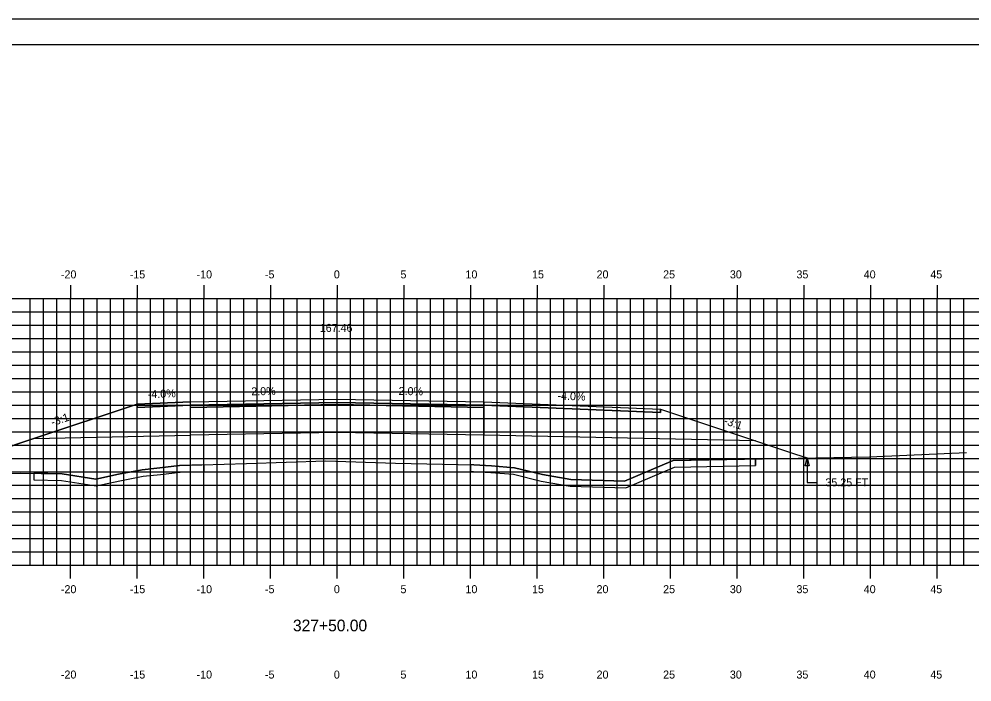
# Model space of a CAD drawing. Extents: x 1140759 to 1140929, y 608981 to 609091.
# Drawn here: x 1140818.2 to 1140889.6, y 609041.6 to 609091.3 of the extents above; entities that cross this region are included whole.
import ezdxf

# ---------------------------------------------------------------- set-up
doc = ezdxf.new("R2010")
doc.units = 0
for name, color, linetype in [('ANNOTATION', 7, 'Continuous'), ('BORDER', 7, 'Continuous'), ('D_Roadway_Centerline', 7, 'Continuous'), ('D_Roadway_Centerline_Text', 7, 'Continuous'), ('D_Roadway_Edge_Shoulder', 7, 'Continuous'), ('D_Roadway_Edge_TW', 7, 'Continuous'), ('D_Roadway_Pavement', 7, 'Continuous'), ('D_Roadway_SlopeLines', 7, 'Continuous'), ('D_Roadway_SubGrade', 7, 'Continuous'), ('D_Text_Standard', 7, 'Continuous'), ('H_V ANNOTATION', 7, 'Continuous'), ('MAJOR', 7, 'Continuous'), ('MINOR', 7, 'Continuous'), ('PLOT BOUNDARY', 7, 'Continuous'), ('S_Roadway_Centerline', 7, 'Continuous'), ('SHADING', 7, 'Continuous')]:
    doc.layers.add(name, color=color, linetype=linetype)

msp = doc.modelspace()

# ---------------------------------------------------------------- linework, layer by layer
msp.add_lwpolyline([(1140811.365, 609057.2), (1140816.276, 609058.837), (1140819.276, 609059.837), (1140827, 609062.411), (1140827.001, 609062.412), (1140831.001, 609062.572), (1140842.001, 609062.792), (1140853.001, 609062.572), (1140866.241, 609062.042), (1140873.375, 609059.664), (1140876.375, 609058.664), (1140877.252, 609058.372)])
at = {"layer": 'BORDER'}
msp.add_lwpolyline([(1140767.001, 608984.335), (1140927.001, 608984.335), (1140927.001, 609089.335), (1140767.001, 609089.335)], close=True, dxfattribs=at)
at = {"layer": 'D_Roadway_Edge_Shoulder'}
for points in [[(1140831.001, 609062.572), (1140827.001, 609062.412), (1140827.001, 609062.162), (1140831.001, 609062.322)], [(1140853.001, 609062.572), (1140866.241, 609062.042), (1140866.241, 609061.792), (1140853.001, 609062.322)]]:
    msp.add_lwpolyline(points, close=True, dxfattribs=at)
at = {"layer": 'D_Roadway_Edge_TW'}
msp.add_lwpolyline([(1140831.001, 609062.322), (1140831.001, 609062.572), (1140842.001, 609062.792), (1140853.001, 609062.572), (1140853.001, 609062.322), (1140842.001, 609062.542)], close=True, dxfattribs=at)
at = {"layer": 'D_Roadway_Pavement'}
msp.add_lwpolyline([(1140831.001, 609062.155), (1140831.001, 609062.322), (1140842.001, 609062.542), (1140853.001, 609062.322), (1140853.001, 609062.155), (1140842.001, 609062.375)], close=True, dxfattribs=at)
at = {"layer": 'D_Roadway_SlopeLines'}
for p, q in [((1140873.375, 609058.298), (1140873.375, 609057.798)), ((1140832.001, 609057.85), (1140832.001, 609057.35)), ((1140852.001, 609057.862), (1140852.001, 609057.362)), ((1140819.276, 609057.222), (1140819.276, 609056.722))]:
    msp.add_line(p, q, dxfattribs=at)
for points in [[(1140819.276, 609059.837), (1140816.276, 609058.837)], [(1140873.375, 609059.664), (1140876.375, 609058.664)], [(1140876.375, 609058.664), (1140877.252, 609058.372)], [(1140852.001, 609057.362), (1140852.225, 609057.357), (1140853.538, 609057.272), (1140855.215, 609057.147), (1140857.304, 609056.635), (1140859.464, 609056.256), (1140863.641, 609056.133), (1140867.31, 609057.681), (1140873.375, 609057.797)], [(1140819.276, 609056.723), (1140821.351, 609056.691), (1140823.935, 609056.277), (1140825.718, 609056.669), (1140827.469, 609057), (1140828.757, 609057.134), (1140830.231, 609057.298), (1140832.001, 609057.351)]]:
    msp.add_lwpolyline(points, dxfattribs=at)
at = {"layer": 'D_Roadway_SubGrade'}
for points in [[(1140831.001, 609062.155), (1140831.001, 609062.322), (1140827.001, 609062.162), (1140827.001, 609062.412), (1140827, 609062.411), (1140819.276, 609059.837), (1140831.001, 609060.071)], [(1140831.001, 609060.071), (1140831.001, 609062.155), (1140842.001, 609062.375), (1140853.001, 609062.155), (1140853.001, 609060.072), (1140842.001, 609060.292)], [(1140853.001, 609062.155), (1140853.001, 609062.322), (1140866.241, 609061.792), (1140866.241, 609062.042), (1140866.241, 609062.042), (1140873.375, 609059.664), (1140853.001, 609060.072)]]:
    msp.add_lwpolyline(points, close=True, dxfattribs=at)
at = {"layer": 'D_Text_Standard'}
msp.add_lwpolyline([(1140877.252, 609058.372), (1140877.397, 609057.79), (1140877.106, 609057.79)], close=True, dxfattribs=at)
msp.add_lwpolyline([(1140877.252, 609058.372), (1140877.251, 609056.542), (1140877.931, 609056.542)], dxfattribs=at)
at = {"layer": 'MAJOR'}
for p, q in [((1140822.001, 609071.337), (1140822.001, 609070.335)), ((1140827.001, 609071.337), (1140827.001, 609070.335)), ((1140832.001, 609071.337), (1140832.001, 609070.335)), ((1140837.001, 609071.337), (1140837.001, 609070.335)), ((1140842.001, 609071.337), (1140842.001, 609070.335)), ((1140847.001, 609071.337), (1140847.001, 609070.335)), ((1140852.001, 609071.337), (1140852.001, 609070.335)), ((1140857.001, 609071.337), (1140857.001, 609070.335)), ((1140862.001, 609071.337), (1140862.001, 609070.335)), ((1140867.001, 609071.337), (1140867.001, 609070.335)), ((1140872.001, 609071.337), (1140872.001, 609070.335)), ((1140877.001, 609071.337), (1140877.001, 609070.335)), ((1140882.001, 609071.337), (1140882.001, 609070.335)), ((1140887.001, 609071.337), (1140887.001, 609070.335)), ((1140772.001, 609070.335), (1140912.001, 609070.335)), ((1140772.001, 609070.335), (1140912.001, 609070.335)), ((1140822.001, 609050.335), (1140822.001, 609070.335)), ((1140827.001, 609050.335), (1140827.001, 609070.335)), ((1140832.001, 609050.335), (1140832.001, 609070.335)), ((1140837.001, 609050.335), (1140837.001, 609070.335)), ((1140842.001, 609050.335), (1140842.001, 609070.335)), ((1140847.001, 609050.335), (1140847.001, 609070.335)), ((1140852.001, 609050.335), (1140852.001, 609070.335)), ((1140857.001, 609050.335), (1140857.001, 609070.335)), ((1140862.001, 609050.335), (1140862.001, 609070.335)), ((1140867.001, 609050.335), (1140867.001, 609070.335)), ((1140872.001, 609050.335), (1140872.001, 609070.335)), ((1140877.001, 609050.335), (1140877.001, 609070.335)), ((1140882.001, 609050.335), (1140882.001, 609070.335)), ((1140887.001, 609050.335), (1140887.001, 609070.335)), ((1140772.001, 609065.335), (1140912.001, 609065.335)), ((1140772.001, 609060.335), (1140912.001, 609060.335)), ((1140772.001, 609055.335), (1140912.001, 609055.335)), ((1140772.001, 609050.335), (1140912.001, 609050.335)), ((1140772.001, 609050.335), (1140912.001, 609050.335)), ((1140822.001, 609049.333), (1140822.001, 609050.335)), ((1140827.001, 609049.333), (1140827.001, 609050.335)), ((1140832.001, 609049.333), (1140832.001, 609050.335)), ((1140837.001, 609049.333), (1140837.001, 609050.335)), ((1140842.001, 609049.333), (1140842.001, 609050.335)), ((1140847.001, 609049.333), (1140847.001, 609050.335)), ((1140852.001, 609049.333), (1140852.001, 609050.335)), ((1140857.001, 609049.333), (1140857.001, 609050.335)), ((1140862.001, 609049.333), (1140862.001, 609050.335)), ((1140867.001, 609049.333), (1140867.001, 609050.335)), ((1140872.001, 609049.333), (1140872.001, 609050.335)), ((1140877.001, 609049.333), (1140877.001, 609050.335)), ((1140882.001, 609049.333), (1140882.001, 609050.335)), ((1140887.001, 609049.333), (1140887.001, 609050.335))]:
    msp.add_line(p, q, dxfattribs=at)
at = {"layer": 'MINOR'}
for p, q in [((1140819.001, 609050.335), (1140819.001, 609070.335)), ((1140820.001, 609050.335), (1140820.001, 609070.335)), ((1140821.001, 609050.335), (1140821.001, 609070.335)), ((1140823.001, 609050.335), (1140823.001, 609070.335)), ((1140824.001, 609050.335), (1140824.001, 609070.335)), ((1140825.001, 609050.335), (1140825.001, 609070.335)), ((1140826.001, 609050.335), (1140826.001, 609070.335)), ((1140828.001, 609050.335), (1140828.001, 609070.335)), ((1140829.001, 609050.335), (1140829.001, 609070.335)), ((1140830.001, 609050.335), (1140830.001, 609070.335)), ((1140831.001, 609050.335), (1140831.001, 609070.335)), ((1140833.001, 609050.335), (1140833.001, 609070.335)), ((1140834.001, 609050.335), (1140834.001, 609070.335)), ((1140835.001, 609050.335), (1140835.001, 609070.335)), ((1140836.001, 609050.335), (1140836.001, 609070.335)), ((1140838.001, 609050.335), (1140838.001, 609070.335)), ((1140839.001, 609050.335), (1140839.001, 609070.335)), ((1140840.001, 609050.335), (1140840.001, 609070.335)), ((1140841.001, 609050.335), (1140841.001, 609070.335)), ((1140843.001, 609050.335), (1140843.001, 609070.335)), ((1140844.001, 609050.335), (1140844.001, 609070.335)), ((1140845.001, 609050.335), (1140845.001, 609070.335)), ((1140846.001, 609050.335), (1140846.001, 609070.335)), ((1140848.001, 609050.335), (1140848.001, 609070.335)), ((1140849.001, 609050.335), (1140849.001, 609070.335)), ((1140850.001, 609050.335), (1140850.001, 609070.335)), ((1140851.001, 609050.335), (1140851.001, 609070.335)), ((1140853.001, 609050.335), (1140853.001, 609070.335)), ((1140854.001, 609050.335), (1140854.001, 609070.335)), ((1140855.001, 609050.335), (1140855.001, 609070.335)), ((1140856.001, 609050.335), (1140856.001, 609070.335)), ((1140858.001, 609050.335), (1140858.001, 609070.335)), ((1140859.001, 609050.335), (1140859.001, 609070.335)), ((1140860.001, 609050.335), (1140860.001, 609070.335)), ((1140861.001, 609050.335), (1140861.001, 609070.335)), ((1140863.001, 609050.335), (1140863.001, 609070.335)), ((1140864.001, 609050.335), (1140864.001, 609070.335)), ((1140865.001, 609050.335), (1140865.001, 609070.335)), ((1140866.001, 609050.335), (1140866.001, 609070.335)), ((1140868.001, 609050.335), (1140868.001, 609070.335)), ((1140869.001, 609050.335), (1140869.001, 609070.335)), ((1140870.001, 609050.335), (1140870.001, 609070.335)), ((1140871.001, 609050.335), (1140871.001, 609070.335)), ((1140873.001, 609050.335), (1140873.001, 609070.335)), ((1140874.001, 609050.335), (1140874.001, 609070.335)), ((1140875.001, 609050.335), (1140875.001, 609070.335)), ((1140876.001, 609050.335), (1140876.001, 609070.335)), ((1140878.001, 609050.335), (1140878.001, 609070.335)), ((1140879.001, 609050.335), (1140879.001, 609070.335)), ((1140880.001, 609050.335), (1140880.001, 609070.335)), ((1140881.001, 609050.335), (1140881.001, 609070.335)), ((1140883.001, 609050.335), (1140883.001, 609070.335)), ((1140884.001, 609050.335), (1140884.001, 609070.335)), ((1140885.001, 609050.335), (1140885.001, 609070.335)), ((1140886.001, 609050.335), (1140886.001, 609070.335)), ((1140888.001, 609050.335), (1140888.001, 609070.335)), ((1140889.001, 609050.335), (1140889.001, 609070.335)), ((1140772.001, 609069.335), (1140912.001, 609069.335)), ((1140772.001, 609068.335), (1140912.001, 609068.335)), ((1140772.001, 609067.335), (1140912.001, 609067.335)), ((1140772.001, 609066.335), (1140912.001, 609066.335)), ((1140772.001, 609064.335), (1140912.001, 609064.335)), ((1140772.001, 609063.335), (1140912.001, 609063.335)), ((1140772.001, 609062.335), (1140912.001, 609062.335)), ((1140772.001, 609061.335), (1140912.001, 609061.335)), ((1140772.001, 609059.335), (1140912.001, 609059.335)), ((1140772.001, 609058.335), (1140912.001, 609058.335)), ((1140772.001, 609057.335), (1140912.001, 609057.335)), ((1140772.001, 609056.335), (1140912.001, 609056.335)), ((1140772.001, 609054.335), (1140912.001, 609054.335)), ((1140772.001, 609053.335), (1140912.001, 609053.335)), ((1140772.001, 609052.335), (1140912.001, 609052.335)), ((1140772.001, 609051.335), (1140912.001, 609051.335))]:
    msp.add_line(p, q, dxfattribs=at)
at = {"layer": 'PLOT BOUNDARY'}
msp.add_lwpolyline([(1140758.908, 608981.276), (1140928.908, 608981.276), (1140928.908, 609091.276), (1140758.908, 609091.276)], close=True, dxfattribs=at)
at = {"layer": 'S_Roadway_Centerline'}
msp.add_lwpolyline([(1140801.566, 609057.193), (1140812.339, 609057.2), (1140818.229, 609057.238), (1140821.395, 609057.189), (1140823.921, 609056.785), (1140825.618, 609057.158), (1140827.397, 609057.494), (1140828.704, 609057.63), (1140830.196, 609057.796), (1140835.206, 609057.946), (1140841.168, 609058.151), (1140846.371, 609057.971), (1140852.246, 609057.857), (1140853.573, 609057.771), (1140855.293, 609057.642), (1140857.407, 609057.124), (1140859.515, 609056.755), (1140863.547, 609056.636), (1140867.204, 609058.18), (1140881.91, 609058.461), (1140889.197, 609058.77)], dxfattribs=at)
at = {"layer": 'SHADING'}
for p, q in [((1140873.375, 609058.298), (1140867.204, 609058.18)), ((1140873.375, 609057.798), (1140873.375, 609058.298)), ((1140832.001, 609057.85), (1140830.196, 609057.796)), ((1140832.001, 609057.35), (1140832.001, 609057.85)), ((1140852.001, 609057.862), (1140852.001, 609057.362)), ((1140819.276, 609057.222), (1140819.276, 609056.722))]:
    msp.add_line(p, q, dxfattribs=at)
for points in [[(1140830.196, 609057.796), (1140828.704, 609057.63), (1140827.397, 609057.494), (1140825.618, 609057.158), (1140823.921, 609056.785), (1140821.395, 609057.189), (1140819.276, 609057.222)], [(1140867.204, 609058.18), (1140863.547, 609056.636), (1140859.515, 609056.755), (1140857.407, 609057.124), (1140855.293, 609057.642), (1140853.573, 609057.771), (1140852.246, 609057.857), (1140852.001, 609057.862)], [(1140852.001, 609057.362), (1140852.225, 609057.357), (1140853.538, 609057.272), (1140855.215, 609057.147), (1140857.304, 609056.635), (1140859.464, 609056.256), (1140863.641, 609056.133), (1140867.31, 609057.681), (1140873.375, 609057.798)], [(1140819.276, 609056.722), (1140821.351, 609056.691), (1140823.935, 609056.277), (1140825.718, 609056.669), (1140827.469, 609057), (1140828.757, 609057.134), (1140830.231, 609057.298), (1140832.001, 609057.35)]]:
    msp.add_lwpolyline(points, dxfattribs=at)

# ---------------------------------------------------------------- texts
at = {"layer": 'ANNOTATION'}
for s, rotation, p in [('-4.0%', 2.29061, (1140827.817, 609062.845)), ('-2.0%', 1.14576, (1140835.304, 609063.058)), ('-2.0%', 358.85424, (1140846.344, 609063.105)), ('-4.0%', 357.70939, (1140858.517, 609062.752)), ('-3:1', 18.43482, (1140820.655, 609060.751)), ('-3:1', 341.56522, (1140870.958, 609060.924))]:
    msp.add_text(s, height=0.6, rotation=rotation, dxfattribs=at).set_placement(p)
at = {"layer": 'D_Roadway_Centerline'}
for s, p in [('C', (1140841.996, 609062.792)), ('C', (1140841.996, 609062.792)), ('L', (1140842.001, 609062.784)), ('L', (1140842.001, 609062.784))]:
    msp.add_text(s, height=0.0146, dxfattribs=at).set_placement(p)
at = {"layer": 'D_Roadway_Centerline_Text'}
msp.add_text('167.46', height=0.6, dxfattribs=at).set_placement((1140840.701, 609067.824))
at = {"layer": 'D_Text_Standard'}
msp.add_text('35.25 FT', height=0.6, dxfattribs=at).set_placement((1140878.611, 609056.242))
at = {"layer": 'H_V ANNOTATION'}
for s, height, p in [('-20', 0.6, (1140821.295, 609071.835)), ('-15', 0.6, (1140826.458, 609071.835)), ('-10', 0.6, (1140831.466, 609071.835)), ('-5', 0.6, (1140836.592, 609071.835)), ('0', 0.6, (1140841.76, 609071.835)), ('5', 0.6, (1140846.752, 609071.835)), ('10', 0.6, (1140851.626, 609071.835)), ('15', 0.6, (1140856.618, 609071.835)), ('20', 0.6, (1140861.455, 609071.835)), ('25', 0.6, (1140866.447, 609071.835)), ('30', 0.6, (1140871.45, 609071.835)), ('35', 0.6, (1140876.442, 609071.835)), ('40', 0.6, (1140881.487, 609071.835)), ('45', 0.6, (1140886.479, 609071.835)), ('-20', 0.6, (1140821.295, 609048.235)), ('-15', 0.6, (1140826.458, 609048.235)), ('-10', 0.6, (1140831.466, 609048.235)), ('-5', 0.6, (1140836.592, 609048.235)), ('0', 0.6, (1140841.76, 609048.235)), ('5', 0.6, (1140846.752, 609048.235)), ('10', 0.6, (1140851.626, 609048.235)), ('15', 0.6, (1140856.618, 609048.235)), ('20', 0.6, (1140861.455, 609048.235)), ('25', 0.6, (1140866.447, 609048.235)), ('30', 0.6, (1140871.45, 609048.235)), ('35', 0.6, (1140876.442, 609048.235)), ('40', 0.6, (1140881.487, 609048.235)), ('45', 0.6, (1140886.479, 609048.235)), ('327+50.00', 0.875, (1140838.692, 609045.378)), ('-20', 0.6, (1140821.295, 609041.835)), ('-15', 0.6, (1140826.458, 609041.835)), ('-10', 0.6, (1140831.466, 609041.835)), ('-5', 0.6, (1140836.592, 609041.835)), ('0', 0.6, (1140841.76, 609041.835)), ('5', 0.6, (1140846.752, 609041.835)), ('10', 0.6, (1140851.626, 609041.835)), ('15', 0.6, (1140856.618, 609041.835)), ('20', 0.6, (1140861.455, 609041.835)), ('25', 0.6, (1140866.447, 609041.835)), ('30', 0.6, (1140871.45, 609041.835)), ('35', 0.6, (1140876.442, 609041.835)), ('40', 0.6, (1140881.487, 609041.835)), ('45', 0.6, (1140886.479, 609041.835))]:
    msp.add_text(s, height=height, dxfattribs=at).set_placement(p)
at = {"layer": 'S_Roadway_Centerline'}
for s, p in [('L', (1140841.16, 609058.143)), ('C', (1140841.163, 609058.151))]:
    msp.add_text(s, height=0.0146, dxfattribs=at).set_placement(p)

doc.saveas('drawing.dxf')
